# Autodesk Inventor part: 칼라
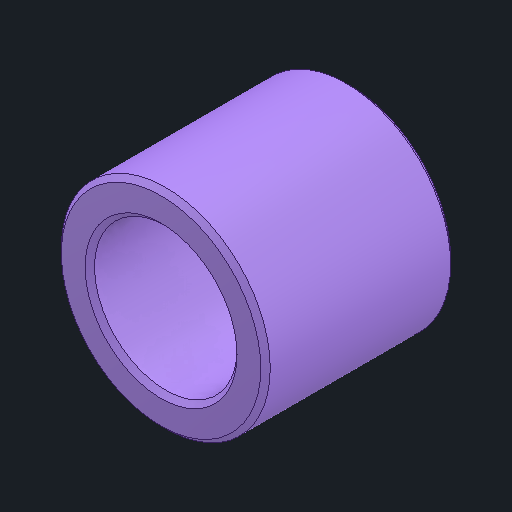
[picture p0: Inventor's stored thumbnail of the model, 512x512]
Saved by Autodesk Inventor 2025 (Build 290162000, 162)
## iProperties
Created: 2025-08
Part Number: 칼라
Material: 스테인리스강
Document SubType Name: Modeling
Designer: infra10
Density: 8.08 g/cm^3
Appearance: 기본값
Author: jhkim
Sending System: Autodesk Inventor 2026
Preprocessor: ST-DEVELOPER v20.1
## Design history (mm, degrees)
feature "솔리드1"
node "솔리드2"
